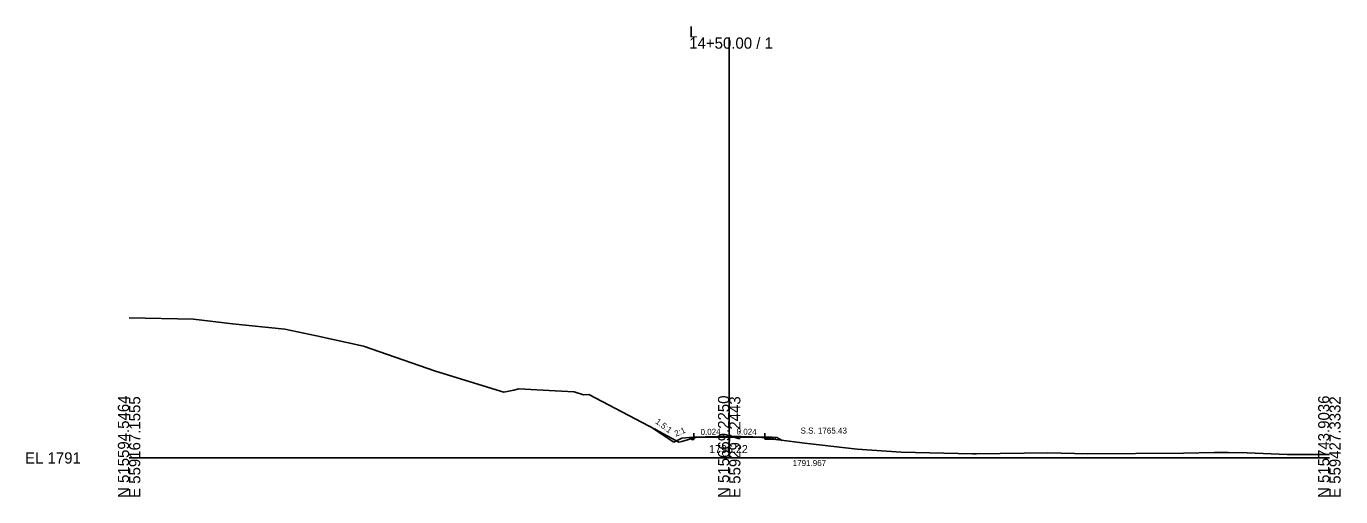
# Model space of a CAD drawing. Extents: x -26 to 1303, y -10 to 9545.
# Drawn here: x 974.3 to 1302.8, y 1990.3 to 2107.9 of the extents above; entities that cross this region are included whole.
import ezdxf

# ---------------------------------------------------------------- set-up
doc = ezdxf.new("R2010")
doc.units = 0
for name, color, linetype in [('Exist Cross Section Cell', 7, 'Continuous'), ('Exist XS Center Line Elevation Label', 7, 'Continuous'), ('Exist XS Ground Line', 7, 'Continuous'), ('Prop XS Ditch Slope Text', 7, 'Continuous'), ('Prop XS Ditch Standard Text', 7, 'Continuous'), ('Prop XS Dump Level', 7, 'Continuous'), ('Prop XS EOT Tick Mark', 7, 'Continuous'), ('Prop XS Finish Grade', 7, 'Continuous'), ('Prop XS Finish Grade Earthwork', 7, 'Continuous'), ('Prop XS Finish Grade Paved Shoulder', 7, 'Continuous'), ('Prop XS Finish Grade Pavement', 7, 'Continuous'), ('Prop XS Pvmt Edge Slope', 7, 'Continuous'), ('Prop XS SE Text', 7, 'Continuous'), ('Prop XS SS Elevation Text', 7, 'Continuous'), ('Prop XS Subgrade Earthwork', 7, 'Continuous')]:
    doc.layers.add(name, color=color, linetype=linetype)

msp = doc.modelspace()

# ---------------------------------------------------------------- linework, layer by layer
at = {"layer": 'Exist Cross Section Cell'}
for p, q in [((1150, 2000), (1150, 2105.1)), ((1000, 2000), (1150, 2000)), ((1150, 2000), (1300, 2000))]:
    msp.add_line(p, q, dxfattribs=at)
at = {"layer": 'Exist XS Ground Line'}
for p, q in [((1000, 2035.03), (1016.07, 2034.65)), ((1016.07, 2034.65), (1025.84, 2033.55)), ((1025.84, 2033.55), (1038.9, 2032.2)), ((1038.9, 2032.2), (1046.88, 2030.56)), ((1046.88, 2030.56), (1058.58, 2027.98)), ((1058.58, 2027.98), (1076.55, 2021.73)), ((1076.55, 2021.73), (1093.7, 2016.44)), ((1096.16, 2016.96), (1097.41, 2017.25)), ((1097.41, 2017.25), (1106.53, 2016.77)), ((1093.7, 2016.44), (1096.16, 2016.96)), ((1106.53, 2016.77), (1111.21, 2016.52)), ((1111.21, 2016.52), (1113.6, 2015.79)), ((1113.6, 2015.79), (1114.89, 2015.82)), ((1114.89, 2015.82), (1131.57, 2007.15)), ((1131.57, 2007.15), (1137.41, 2003.95)), ((1137.41, 2003.95), (1138.12, 2004.14)), ((1138.12, 2004.14), (1141.54, 2005.09)), ((1141.54, 2005.09), (1146.06, 2005.16)), ((1146.06, 2005.16), (1149.93, 2005.22)), ((1149.93, 2005.22), (1153.83, 2005.16)), ((1153.83, 2005.16), (1158.18, 2005.12)), ((1158.18, 2005.12), (1161.63, 2004.6)), ((1161.63, 2004.6), (1169.57, 2003.58)), ((1169.57, 2003.58), (1182.02, 2002.22)), ((1182.02, 2002.22), (1193, 2001.48)), ((1193, 2001.48), (1210.83, 2000.99)), ((1210.83, 2000.99), (1211.81, 2001)), ((1211.81, 2001), (1229.67, 2001.28)), ((1229.67, 2001.28), (1239.65, 2001)), ((1239.65, 2001), (1263.53, 2001.21)), ((1263.53, 2001.21), (1271.28, 2001.33)), ((1271.28, 2001.33), (1274.72, 2001.36)), ((1274.72, 2001.36), (1279.45, 2001.28)), ((1279.45, 2001.28), (1289.44, 2000.9)), ((1289.44, 2000.9), (1300, 2000.88))]:
    msp.add_line(p, q, dxfattribs=at)
at = {"layer": 'Prop XS Dump Level'}
for p, q in [((1140.87, 2005.15), (1150, 2005.42)), ((1150, 2005.42), (1158.88, 2005.21))]:
    msp.add_line(p, q, dxfattribs=at)
at = {"layer": 'Prop XS EOT Tick Mark'}
for p, q in [((1141.12, 2005.16), (1141.12, 2006.16)), ((1158.91, 2005.21), (1158.91, 2006.21))]:
    msp.add_line(p, q, dxfattribs=at)
at = {"layer": 'Prop XS Finish Grade'}
for p, q in [((1141.12, 2005.16), (1140.09, 2005.07)), ((1160.69, 2005.16), (1161.72, 2005.08))]:
    msp.add_line(p, q, dxfattribs=at)
at = {"layer": 'Prop XS Finish Grade Earthwork'}
for p, q in [((1136.12, 2003.92), (1130.23, 2007.84)), ((1138.12, 2004.92), (1136.12, 2003.92)), ((1140.09, 2005.07), (1138.12, 2004.92)), ((1161.72, 2005.08), (1161.91, 2005.07)), ((1161.91, 2005.07), (1163.26, 2004.39))]:
    msp.add_line(p, q, dxfattribs=at)
at = {"layer": 'Prop XS Finish Grade Paved Shoulder'}
msp.add_line((1158.91, 2005.21), (1160.69, 2005.16), dxfattribs=at)
at = {"layer": 'Prop XS Finish Grade Pavement'}
for p, q in [((1141.12, 2005.16), (1150, 2005.42)), ((1150, 2005.42), (1158.91, 2005.21))]:
    msp.add_line(p, q, dxfattribs=at)
at = {"layer": 'Prop XS Pvmt Edge Slope'}
for p, q in [((1141.12, 2005.16), (1140.56, 2004.6)), ((1160.69, 2005.16), (1161.25, 2004.61))]:
    msp.add_line(p, q, dxfattribs=at)
at = {"layer": 'Prop XS Subgrade Earthwork'}
for p, q in [((1140.56, 2004.6), (1140.09, 2005.07)), ((1141.12, 2004.61), (1140.56, 2004.6)), ((1141.12, 2004.61), (1141.12, 2004.97)), ((1158.91, 2004.67), (1158.91, 2005.01)), ((1158.91, 2004.67), (1161.25, 2004.61)), ((1161.25, 2004.61), (1161.72, 2005.08))]:
    msp.add_line(p, q, dxfattribs=at)

# ---------------------------------------------------------------- texts
at = {"layer": 'Exist Cross Section Cell'}
for s, p in [('L', (1140, 2105.1)), ('14+50.00 / 1', (1140, 2102.3)), ('EL 1791', (974, 1998.6))]:
    msp.add_text(s, height=2.8, dxfattribs=at).set_placement(p)
for s, p in [('N 515594.5464', (1000, 1990)), ('E 559167.1555', (1002.8, 1990)), ('N 515669.2250', (1150, 1990)), ('E 559297.2443', (1152.8, 1990)), ('N 515743.9036', (1300, 1990)), ('E 559427.3332', (1302.8, 1990))]:
    msp.add_text(s, height=2.8, rotation=90, dxfattribs=at).set_placement(p)
at = {"layer": 'Exist XS Center Line Elevation Label'}
msp.add_text('1796.22', height=2, dxfattribs=at).set_placement((1144.98, 2001.22))
at = {"layer": 'Prop XS Ditch Slope Text'}
for s, rotation, p in [('1.5:1', 323.3447, (1131.42, 2008.76)), ('2:1', 23.9713, (1136.7, 2005.28))]:
    msp.add_text(s, height=1.5, rotation=rotation, dxfattribs=at).set_placement(p)
at = {"layer": 'Prop XS Ditch Standard Text'}
msp.add_text('1791.967', height=1.5, dxfattribs=at).set_placement((1165.86, 1997.97))
at = {"layer": 'Prop XS Dump Level'}
for s, height, p in [('Eop', 0.3, (1130.87, 2007.21)), ('Case1', 0.04, (1137.87, 2004.87)), ('Case1', 0.04, (1161.88, 2004.93)), ('Eop', 0.3, (1168.88, 2003.37))]:
    msp.add_text(s, height=height, dxfattribs=at).set_placement(p)
at = {"layer": 'Prop XS SE Text'}
for rotation, p in [(1.7184, (1142.85, 2005.71)), (358.6175, (1151.82, 2005.88))]:
    msp.add_text('0.024', height=1.5, rotation=rotation, dxfattribs=at).set_placement(p)
at = {"layer": 'Prop XS SS Elevation Text'}
msp.add_text('S.S. 1765.43', height=1.5, dxfattribs=at).set_placement((1167.83, 2006.09))

doc.saveas('drawing.dxf')
